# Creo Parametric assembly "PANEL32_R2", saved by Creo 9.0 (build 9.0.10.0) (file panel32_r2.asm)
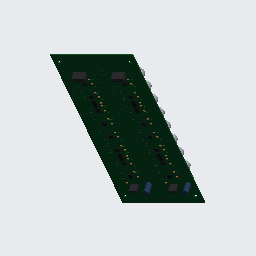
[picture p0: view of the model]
Units: millimeter Newton Second (mmNs); MM, TONNE, SECS

Created from: MMNS_ASM_DESIGN_ABS.ASM

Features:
  1. datum plane "ASM_RIGHT"
  2. datum plane "ASM_TOP"
  3. datum plane "ASM_FRONT"
  4. coordinate system
  5. coordinate system
  6. component "PCB32_R2"
  7. coordinate system
  8. component "C0805_R1"
  9. coordinate system
  10. component "C0805_R1"
  11. coordinate system
  12. component "C0805_R1"
  13. coordinate system
  14. component "C0805_R1"
  15. coordinate system
  16. component "C0805_R1"
  17. coordinate system
  18. component "C0805_R1"
  19. coordinate system
  20. component "C0805_R1"
  21. coordinate system
  22. component "C0805_R1"
  23. coordinate system
  24. component "C0805_R1"
  25. coordinate system
  26. component "C0805_R1"
  27. coordinate system
  28. component "CP63_R1"
  29. coordinate system
  30. component "C0805_R1"
  31. coordinate system
  32. component "C0805_R1"
  33. coordinate system
  34. component "C0805_R1"
  35. coordinate system
  36. component "C0805_R1"
  37. coordinate system
  38. component "C0805_R1"
  39. coordinate system
  40. component "C0805_R1"
  41. coordinate system
  42. component "C0805_R1"
  43. coordinate system
  44. component "C0805_R1"
  45. coordinate system
  46. component "C0805_R1"
  47. coordinate system
  48. component "C0805_R1"
  49. coordinate system
  50. component "C0805_R1"
  51. coordinate system
  52. component "C0805_R1"
  53. coordinate system
  54. component "C0805_R1"
  55. coordinate system
  56. component "C0805_R1"
  57. coordinate system
  58. component "C0805_R1"
  59. coordinate system
  60. component "C0805_R1"
  61. coordinate system
  62. component "C0805_R1"
  63. coordinate system
  64. component "C0805_R1"
  65. coordinate system
  66. component "C0805_R1"
  67. coordinate system
  68. component "C0805_R1"
  69. coordinate system
  70. component "C0805_R1"
  71. coordinate system
  72. component "CP63_R1"
  73. coordinate system
  74. component "C0805_R1"
  75. coordinate system
  76. component "C0805_R1"
  77. coordinate system
  78. component "C0805_R1"
  79. coordinate system
  80. component "C0805_R1"
  81. coordinate system
  82. component "C0805_R1"
  83. coordinate system
  84. component "C0805_R1"
  85. coordinate system
  86. component "C0805_R1"
  87. coordinate system
  88. component "HDR10_R1"
  89. coordinate system
  90. component "HDR10_R1"
  91. coordinate system
  92. component "HDR3_R1"
  93. coordinate system
  94. component "HDR3_R1"
  95. coordinate system
  96. component "SOT23_R1"
  97. coordinate system
  98. component "SOT23_R1"
  99. coordinate system
  100. component "R0805_R1"
  101. coordinate system
  102. component "R0805_R1"
  103. coordinate system
  104. component "R0805_R1"
  105. coordinate system
  106. component "R0805_R1"
  107. coordinate system
  108. component "R0805_R1"
  109. coordinate system
  110. component "R0805_R1"
  111. coordinate system
  112. component "R0805_R1"
  113. coordinate system
  114. component "R0805_R1"
  115. coordinate system
  116. component "R0805_R1"
  117. coordinate system
  118. component "R0805_R1"
  119. coordinate system
  120. component "R0805_R1"
  121. coordinate system
  122. component "R0805_R1"
  123. coordinate system
  124. component "R0805_R1"
  125. coordinate system
  126. component "R0805_R1"
  127. coordinate system
  128. component "R0805_R1"
  129. coordinate system
  130. component "R0805_R1"
  131. coordinate system
  132. component "R0805_R1"
  133. coordinate system
  134. component "R0805_R1"
  135. coordinate system
  136. component "R0805_R1"
  137. coordinate system
  138. component "R0805_R1"
  139. coordinate system
  140. component "R0805_R1"
  141. coordinate system
  142. component "R0805_R1"
  143. coordinate system
  144. component "R0805_R1"
  145. coordinate system
  146. component "R0805_R1"
  147. coordinate system
  148. component "R0805_R1"
  149. coordinate system
  150. component "R0805_R1"
  151. coordinate system
  152. component "R0805_R1"
  153. coordinate system
  154. component "R0805_R1"
  155. coordinate system
  156. component "R0805_R1"
  157. coordinate system
  158. component "R0805_R1"
  159. coordinate system
  160. component "R0805_R1"
  161. coordinate system
  162. component "R0805_R1"
  163. coordinate system
  164. component "R0805_R1"
  165. coordinate system
  166. component "R0805_R1"
  167. coordinate system
  168. component "R0805_R1"
  169. coordinate system
  170. component "R0805_R1"
  171. coordinate system
  172. component "R0805_R1"
  173. coordinate system
  174. component "R0805_R1"
  175. coordinate system
  176. component "R0805_R1"
  177. coordinate system
  178. component "R0805_R1"
  179. coordinate system
  180. component "R0805_R1"
  181. coordinate system
  182. component "R0805_R1"
  183. coordinate system
  184. component "R0805_R1"
  185. coordinate system
  186. component "R0805_R1"
  187. coordinate system
  188. component "R0805_R1"
  189. coordinate system
  190. component "R0805_R1"
  191. coordinate system
  192. component "R0805_R1"
  193. coordinate system
  194. component "R0805_R1"
  195. coordinate system
  196. component "R0805_R1"
  197. coordinate system
  198. component "R0805_R1"
  199. coordinate system
  200. component "TX16_R1"
  201. coordinate system
  202. component "TX16_R1"
  203. coordinate system
  204. component "TX16_R1"
  205. coordinate system
  206. component "TX16_R1"
  207. coordinate system
  208. component "TX16_R1"
  209. coordinate system
  210. component "TX16_R1"
  211. coordinate system
  212. component "TX16_R1"
  213. coordinate system
  214. component "TX16_R1"
  215. coordinate system
  216. component "TX16_R1"
  217. coordinate system
  218. component "TX16_R1"
  219. coordinate system
  220. component "TX16_R1"
  221. coordinate system
  222. component "TX16_R1"
  223. coordinate system
  224. component "TX16_R1"
  225. coordinate system
  226. component "TX16_R1"
  227. coordinate system
  228. component "TX16_R1"
  229. coordinate system
  230. component "TX16_R1"
  231. coordinate system
  232. component "TX16_R1"
  233. coordinate system
  234. component "TX16_R1"
  235. coordinate system
  236. component "TX16_R1"
  237. coordinate system
  238. component "TX16_R1"
  239. coordinate system
  240. component "TX16_R1"
  241. coordinate system
  242. component "TX16_R1"
  243. coordinate system
  244. component "TX16_R1"
  245. coordinate system
  246. component "TX16_R1"
  247. coordinate system
  248. component "TX16_R1"
  249. coordinate system
  250. component "TX16_R1"
  251. coordinate system
  252. component "TX16_R1"
  253. coordinate system
  254. component "TX16_R1"
  255. coordinate system
  256. component "TX16_R1"
  257. coordinate system
  258. component "TX16_R1"
  259. coordinate system
  260. component "TX16_R1"
  261. coordinate system
  262. component "TX16_R1"
  263. coordinate system
  264. component "SO16_R1"
  265. coordinate system
  266. component "SO8_R1"
  267. coordinate system
  268. component "SO8_R1"
  269. coordinate system
  270. component "SO8_R1"
  271. coordinate system
  272. component "SO8_R1"
  273. coordinate system
  274. component "SO8_R1"
  275. coordinate system
  276. component "SO8_R1"
  277. coordinate system
  278. component "SO8_R1"
  279. coordinate system
  280. component "SO8_R1"
  281. coordinate system
  282. component "SO8_R1"
  283. coordinate system
  284. component "SO8_R1"
  285. coordinate system
  286. component "SO16_R1"
  287. coordinate system
  288. component "SO8_R1"
  289. coordinate system
  290. component "SO16_R1"
  291. coordinate system
  292. component "SO16_R1"
  293. coordinate system
  294. component "SO8_R1"
  295. coordinate system
  296. component "SO8_R1"
  297. coordinate system
  298. component "SO8_R1"
  299. coordinate system
  300. component "SO8_R1"
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
Other named items: ACS0, ACS1, ACS2, ACS3, ACS4, ACS5, ACS6, ACS7, ACS8, ACS9, ACS10, ACS11, ACS12, ACS13, ACS14, ACS15, ACS16, ACS17, ACS18, ACS19, ACS20, ACS21, ACS22, ACS23, ACS24, ACS25, ACS26, ACS27, ACS28, ACS29, ACS30, ACS31, ACS32, ACS33, ACS34, ACS35, ACS36, ACS37, ACS38, ACS39, ACS40, ACS41, ACS42, ACS43, ACS44, ACS45, ACS46, ACS47, ACS48, ACS49, ACS50, ACS51, ACS52, ACS53, ACS54, ACS55, ACS56, ACS57, ACS58, ACS59, ACS60, ACS61, ACS62, ACS63, ACS64, ACS65, ACS66, ACS67, ACS68, ACS69, ACS70, ACS71, ACS72, ACS73, ACS74, ACS75, ACS76, ACS77, ACS78, ACS79, ACS80, ACS81, ACS82, ACS83, ACS84, ACS85, ACS86, ACS87, ACS88, ACS89, ACS90, ACS91, ACS92, ACS93, ACS94, ACS95, ACS96, ACS97, ACS98, ACS99, ACS100, ACS101, ACS102, ACS103, ACS104, ACS105, ACS106, ACS107, ACS108, ACS109, ACS110, ACS111, ACS112, ACS113, ACS114, ACS115, ACS116, ACS117, ACS118, ACS119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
